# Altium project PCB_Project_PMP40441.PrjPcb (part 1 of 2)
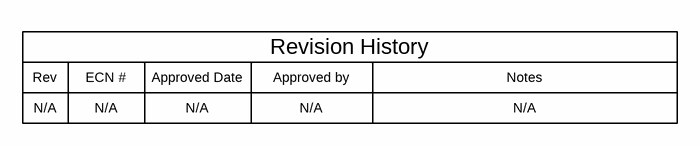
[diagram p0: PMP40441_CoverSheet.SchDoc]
TID: N/A; TechSupport: http://www.ti.com/support; SCH_Rev: E1; PRJ_Title: Multi-cell Buck-boost Battery Charger for PD PPS; PRJ_Number: PMP40441; PRJ_Engineer: San Chen; PRJ_Customer: Public Release; PCB_Rev: E1; PCB_Layout: Who did the Layout?; CopyrightYear: 2017
3 sheets, 208 parts. Net scope: global (net labels, ports and power ports of the same name join across sheets).
Board file: PMP40441_Layout.PcbDoc
Sheets:
  PMP40441_CoverSheet.SchDoc
  PMP40441_Main.SchDoc
  PMP40442_Main.SchDoc

## Sheet PMP40441_CoverSheet.SchDoc
size 431 x 279 mm; Date: Not shown in title block; ApprovedBy: Not shown in title block; CheckedBy: Not shown in title block; Author: Not shown in title block; CompanyName: Not shown in title block; Engineer: Not shown in title block; Organization: Not shown in title block; Address1: Not shown in title block; Address2: Not shown in title block; Address3: Not shown in title block; Address4: Not shown in title block; DocumentNumber: 1; Revision: Use project parameter SCH_Rev; SheetNumber: 1; SheetTotal: 3; PageSetup: Record=PageOptions¦CenterHorizontal=True¦CenterVertical=True¦PrintScale=1.00¦XCorrection=1.00¦YCorrection=1.00¦PrintKind=0¦BorderSize=5000000¦LeftOffset=0¦BottomOffset=0¦Orientation=2¦PaperLength=1000¦PaperWidth=1000¦Scale=100¦PaperSource=15¦PrintQuality=600¦MediaType=1¦DitherType=10¦PaperKind=Letter¦PrintScaleMode=1

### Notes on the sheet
- Rev
- N/A
- ECN #
- Approved Date
- Approved by
- Revision History
- Notes

## Sheet PMP40441_Main.SchDoc
size 431 x 279 mm; Date: Not shown in title block; ApprovedBy: Not shown in title block; CheckedBy: Not shown in title block; Author: Not shown in title block; CompanyName: Not shown in title block; Engineer: Not shown in title block; Organization: Not shown in title block; Address1: Not shown in title block; Address2: Not shown in title block; Address3: Not shown in title block; Address4: Not shown in title block; DocumentNumber: 2; Revision: Use project parameter SCH_Rev; SheetNumber: 2; SheetTotal: 3; PageSetup: Record=PageOptions¦CenterHorizontal=True¦CenterVertical=True¦PrintScale=1.00¦XCorrection=1.00¦YCorrection=1.00¦PrintKind=0¦BorderSize=5000000¦LeftOffset=0¦BottomOffset=0¦Orientation=2¦PaperLength=1000¦PaperWidth=1000¦Scale=100¦PaperSource=15¦PrintQuality=600¦MediaType=1¦DitherType=10¦PaperKind=Letter¦PrintScaleMode=1
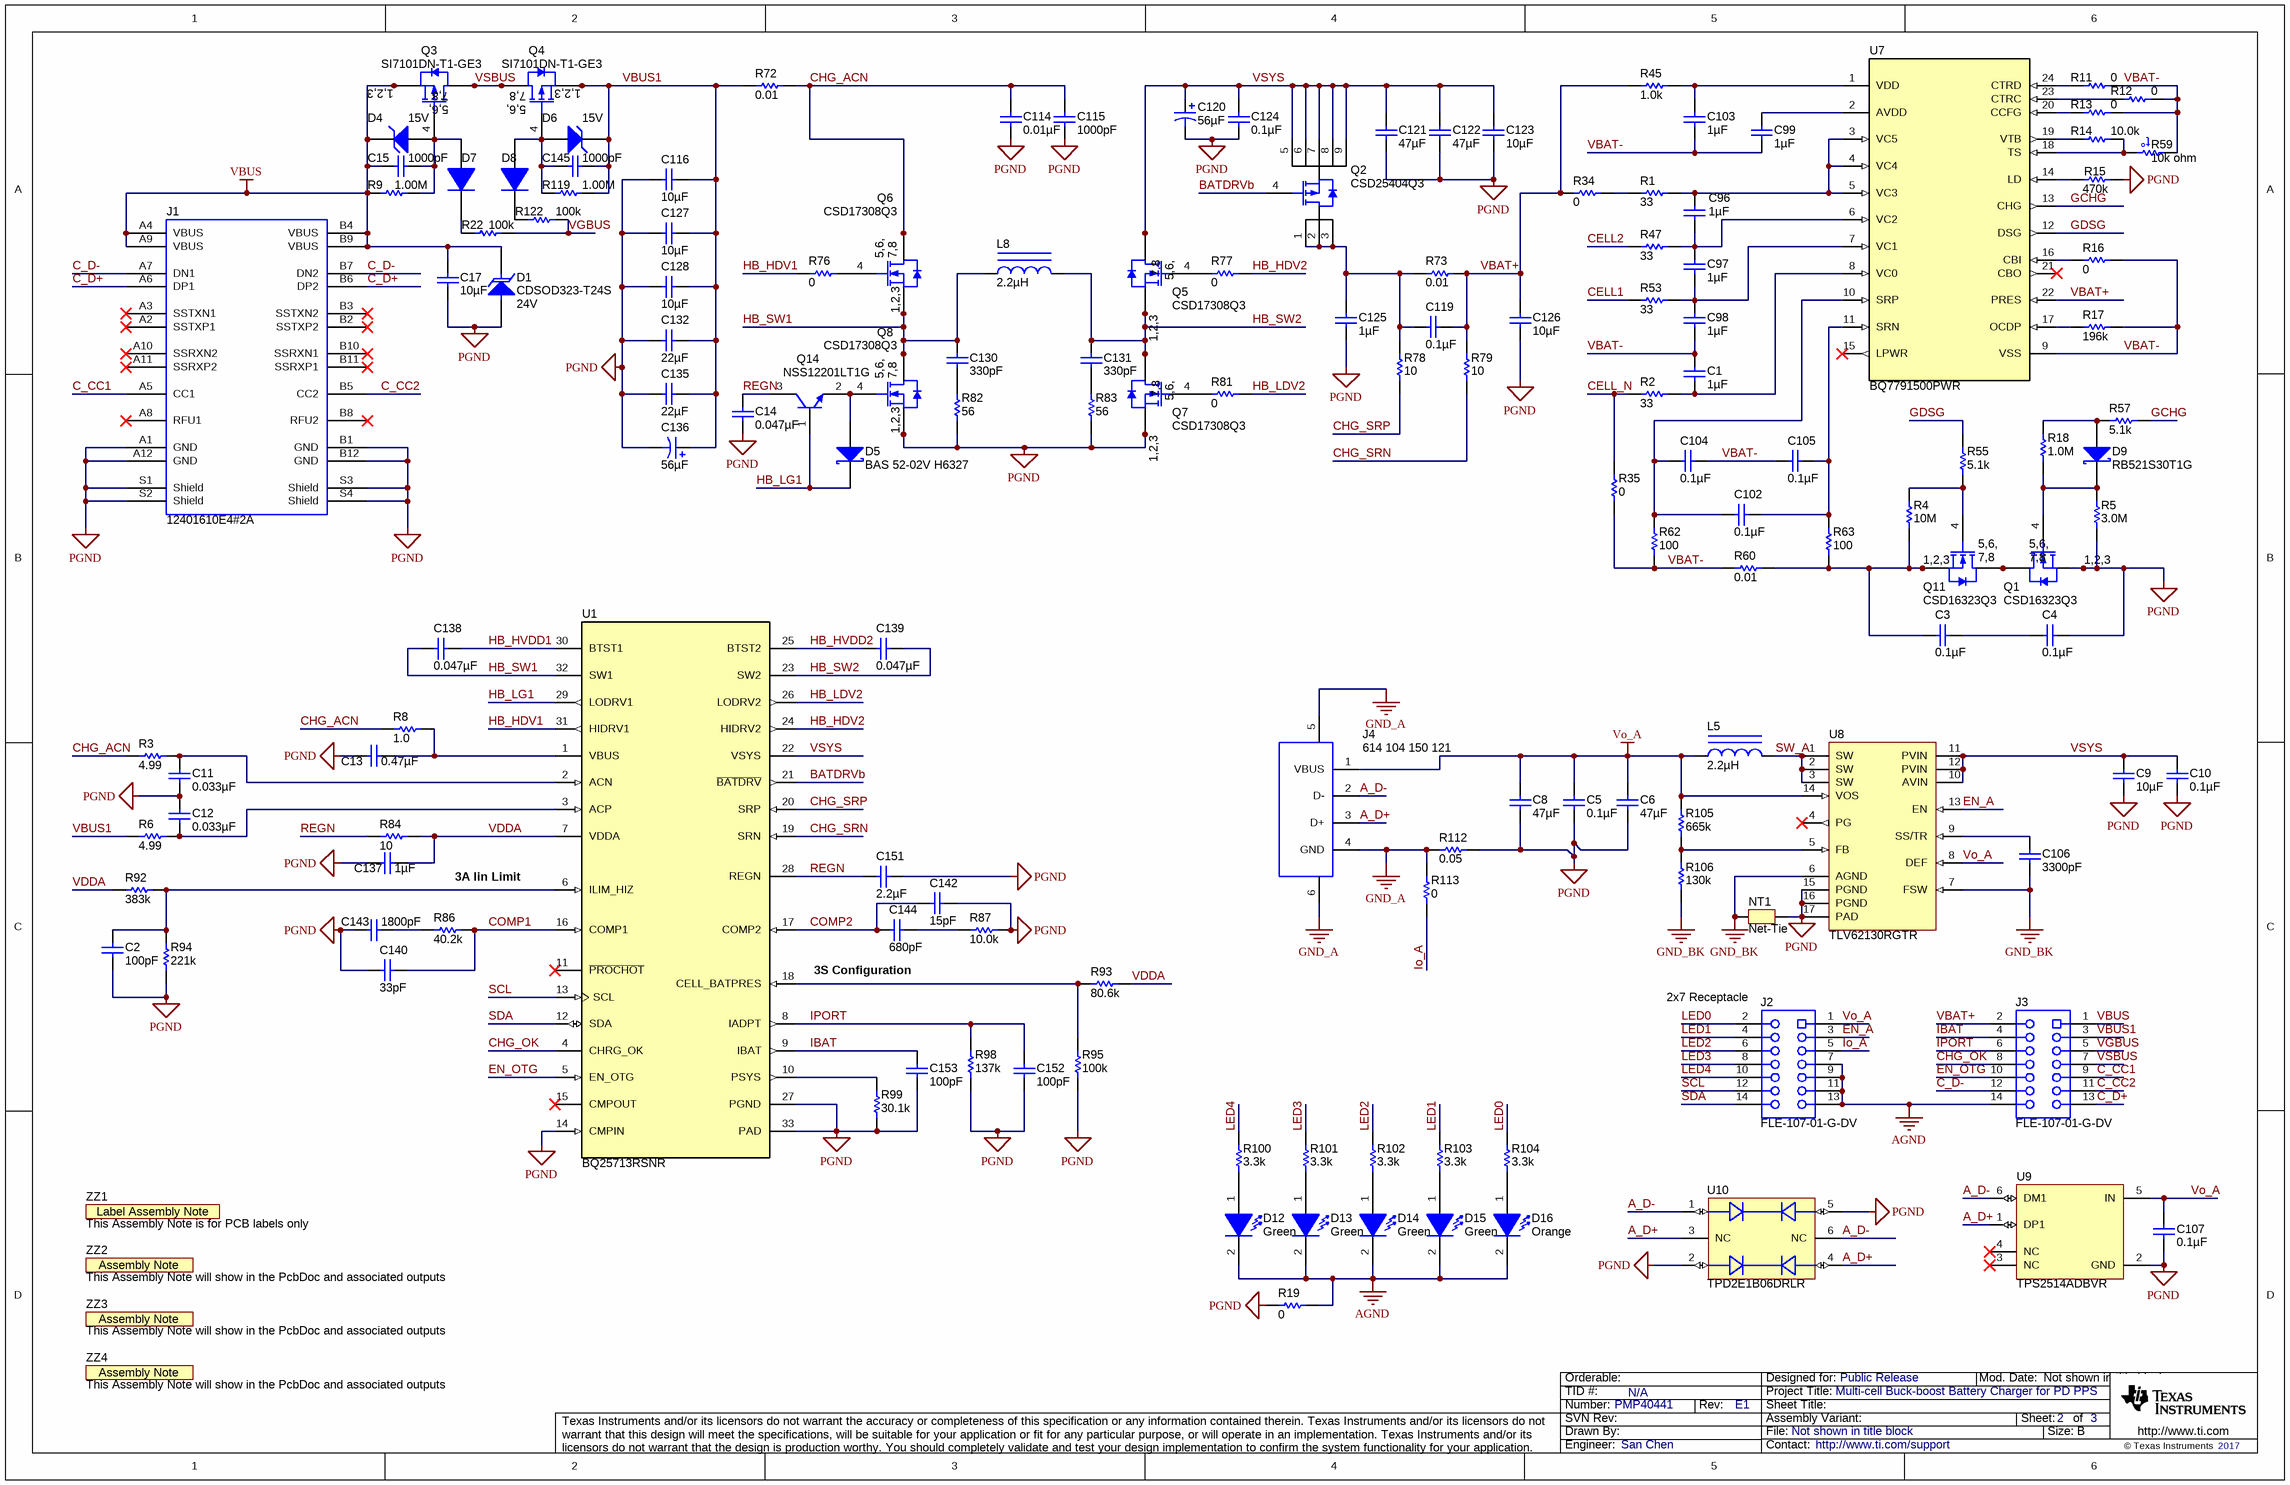
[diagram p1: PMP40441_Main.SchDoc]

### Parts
C1  ValueDisplayed: 1µF  [0402S]  (hidden comment: C1005X5R1C105K050BC)
C2  ValueDisplayed: 100pF  [0402]  (hidden comment: GRM1555C1H101JA01D)
C3  ValueDisplayed: 0.1µF  [0402]  (hidden comment: GRM155R61C104KA88D)
C4  ValueDisplayed: 0.1µF  [0402]  (hidden comment: GRM155R61C104KA88D)
C5  ValueDisplayed: 0.1µF  [0402]  (hidden comment: GRM155R61C104KA88D)
C6  ValueDisplayed: 47µF  [0805_HV]  (hidden comment: JMK212BJ476MG-T)
C8  ValueDisplayed: 47µF  [0805_HV]  (hidden comment: JMK212BJ476MG-T)
C9  ValueDisplayed: 10µF  [0603]  (hidden comment: GRM188R61E106MA73D)
C10  ValueDisplayed: 0.1µF  [0402]  (hidden comment: GRM155R61E104KA87D)
C11  ValueDisplayed: 0.033µF  [0603S]  (hidden comment: GRM188R71H333KA61D)
C12  ValueDisplayed: 0.033µF  [0603S]  (hidden comment: GRM188R71H333KA61D)
C13  ValueDisplayed: 0.47µF  [0805L]  (hidden comment: GRM21BR71H474KA88L)
C14  ValueDisplayed: 0.047µF  [0402]  (hidden comment: GRM155R61C473KA01D)
C15  ValueDisplayed: 1000pF  [0402]  (hidden comment: C0402C102J3RACTU)
C17  ValueDisplayed: 10µF  [0805_HV]  (hidden comment: GRM21BR6YA106KE43L)
C96  ValueDisplayed: 1µF  [0402S]  (hidden comment: C1005X5R1C105K050BC)
C97  ValueDisplayed: 1µF  [0402S]  (hidden comment: C1005X5R1C105K050BC)
C98  ValueDisplayed: 1µF  [0402S]  (hidden comment: C1005X5R1C105K050BC)
C99  ValueDisplayed: 1µF  [0402S]  (hidden comment: C1005X5R1C105K050BC)
C102  ValueDisplayed: 0.1µF  [0402S]  (hidden comment: GRM155R61C104KA88D)
C103  ValueDisplayed: 1µF  [0402S]  (hidden comment: C1005X5R1E105K050BC)
C104  ValueDisplayed: 0.1µF  [0402S]  (hidden comment: GRM155R61C104KA88D)
C105  ValueDisplayed: 0.1µF  [0402S]  (hidden comment: GRM155R61C104KA88D)
C106  ValueDisplayed: 3300pF  [0402]  (hidden comment: GRM155R71H332KA01D)
C107  ValueDisplayed: 0.1µF  [0402]  (hidden comment: GRM155R61C104KA88D)
C114  ValueDisplayed: 0.01µF  [0402S]  (hidden comment: GRM155R71H103KA88D)
C115  ValueDisplayed: 1000pF  [0402S]  (hidden comment: GRM155R61H102KA01D)
C116  ValueDisplayed: 10µF  [0805_HV]  (hidden comment: GRM21BR6YA106KE43L)
C119  ValueDisplayed: 0.1µF  [0402S]  (hidden comment: GRM155R61E104KA87D)
C120  ValueDisplayed: 56µF  [SM_RADIAL_6.3AMM]  (hidden comment: EEHZA1E560P)
C121  ValueDisplayed: 47µF  [1206_190]  (hidden comment: C3216X5R1E476M160AC)
C122  ValueDisplayed: 47µF  [1206_190]  (hidden comment: C3216X5R1E476M160AC)
C123  ValueDisplayed: 10µF  [0603]  (hidden comment: GRM188R61E106MA73D)
C124  ValueDisplayed: 0.1µF  [0402]  (hidden comment: GRM155R61E104KA87D)
C125  ValueDisplayed: 1µF  [0402S]  (hidden comment: GRM155R61E105KA12D)
C126  ValueDisplayed: 10µF  [0603]  (hidden comment: GRM188R61E106MA73D)
C127  ValueDisplayed: 10µF  [0805_HV]  (hidden comment: GRM21BR6YA106KE43L)
C128  ValueDisplayed: 10µF  [0805_HV]  (hidden comment: GRM21BR6YA106KE43L)
C130  ValueDisplayed: 330pF  [0402S]  (hidden comment: GRM1555C1H331JA01D)
C131  ValueDisplayed: 330pF  [0402S]  (hidden comment: GRM1555C1H331JA01D)
C132  ValueDisplayed: 22µF  [1206_190]  (hidden comment: C3216X5R1V226M160AC)
C135  ValueDisplayed: 22µF  [1206_190]  (hidden comment: C3216X5R1V226M160AC)
C136  ValueDisplayed: 56µF  [SM_RADIAL_6.3AMM]  (hidden comment: EEHZA1E560P)
C137  ValueDisplayed: 1µF  [0402]  (hidden comment: C1005X5R1C105K050BC)
C138  ValueDisplayed: 0.047µF  [0402]  (hidden comment: GRM155R61C473KA01D)
C139  ValueDisplayed: 0.047µF  [0402]  (hidden comment: GRM155R61C473KA01D)
C140  ValueDisplayed: 33pF  [0402]  (hidden comment: GRM1555C1H330JA01D)
C142  ValueDisplayed: 15pF  [0402]  (hidden comment: GRM1555C1H150JA01D)
C143  ValueDisplayed: 1800pF  [0402]  (hidden comment: GRM155R71H182KA01D)
C144  ValueDisplayed: 680pF  [0402]  (hidden comment: GRM1555C1H681JA01D)
C145  ValueDisplayed: 1000pF  [0402]  (hidden comment: C0402C102J3RACTU)
C151  ValueDisplayed: 2.2µF  [0402]  (hidden comment: C1005X5R1C225K050BC)
C152  ValueDisplayed: 100pF  [0402]  (hidden comment: GRM1555C1H101JA01D)
C153  ValueDisplayed: 100pF  [0402]  (hidden comment: GRM1555C1H101JA01D)
D1  CDSOD323-T24S  value 24V  [SOD-323]
D4  value 15V  [SOD-323]  (hidden comment: BZX384-C15,115)
D5  BAS 52-02V H6327  [SOD-523]
D6  value 15V  [SOD-323]  (hidden comment: BZX384-C15,115)
D7  1N4148WX-TP  [SOD-323]  (value not drawn)
D8  1N4148WX-TP  [SOD-323]  (value not drawn)
D9  RB521S30T1G  [SOD-523]
D12  value Green  [LED_LTST-C190]  (hidden comment: LTST-C190GKT)
D13  value Green  [LED_LTST-C190]  (hidden comment: LTST-C190GKT)
D14  value Green  [LED_LTST-C190]  (hidden comment: LTST-C190GKT)
D15  value Green  [LED_LTST-C190]  (hidden comment: LTST-C190GKT)
D16  value Orange  [LED_LTST-C190]  (hidden comment: LTST-C190KFKT)
J1  12401610E4#2A  [Amphenol_12401610E4_2A]
J2  FLE-107-01-G-DV  [Samtec_FLE-107-01-x-DV]
J3  FLE-107-01-G-DV  [Samtec_FLE-107-01-x-DV]
J4  614 104 150 121  [WURTH_614104150121]
L5  ValueDisplayed: 2.2µH  [XFL4020]  (hidden comment: XFL4020-222MEB)
L8  ValueDisplayed: 2.2µH  [XEL6060]  (hidden comment: XEL6060-222MEB)
NT1  Net-Tie  [Net-Tie_10mil]  (net tie, no BOM)
Q1  CSD16323Q3  [DQG0008A]
Q2  CSD25404Q3  [DQG0008A]
Q3  SI7101DN-T1-GE3  [PowerPAK_1212-8]
Q4  SI7101DN-T1-GE3  [PowerPAK_1212-8]
Q5  CSD17308Q3  [DQG0008A]
Q6  CSD17308Q3  [DQG0008A]
Q7  CSD17308Q3  [CSD17308Q3]
Q8  CSD17308Q3  [DQG0008A]
Q11  CSD16323Q3  [DQG0008A]
Q14  NSS12201LT1G  [SOT-23]
R1  ValueDisplayed: 33  [0805L]  (hidden comment: CRCW080533R0JNEA)
R2  ValueDisplayed: 33  [0805L]  (hidden comment: CRCW080533R0JNEA)
R3  ValueDisplayed: 4.99  [0402S]  (hidden comment: CRCW04024R99FKED)
R4  ValueDisplayed: 10M  [0402]  (hidden comment: CRCW040210M0JNED)
R5  ValueDisplayed: 3.0M  [0402]  (hidden comment: CRCW04023M00JNED)
R6  ValueDisplayed: 4.99  [0402S]  (hidden comment: CRCW04024R99FKED)
R8  ValueDisplayed: 1.0  [0402]  (hidden comment: CRCW04021R00JNED)
R9  ValueDisplayed: 1.00M  [0402]  (hidden comment: RC0402FR-071ML)
R11  ValueDisplayed: 0  [0402S]  (hidden comment: CRCW04020000Z0ED)
R12  ValueDisplayed: 0  [0402S]  (hidden comment: CRCW04020000Z0ED)
R13  ValueDisplayed: 0  [0402S]  (hidden comment: CRCW04020000Z0ED)
R14  ValueDisplayed: 10.0k  [0402S]  (hidden comment: CRCW040210K0FKED)
R15  ValueDisplayed: 470k  [0402S]  (hidden comment: CRCW0402470KJNED)
R16  ValueDisplayed: 0  [0402S]  (hidden comment: CRCW04020000Z0ED)
R17  ValueDisplayed: 196k  [0402S]  (hidden comment: CRCW0402196KFKED)
R18  ValueDisplayed: 1.0M  [0402]  (hidden comment: CRCW04021M00JNED)
R19  ValueDisplayed: 0  [0402]  (hidden comment: CRCW04020000Z0ED)
R22  ValueDisplayed: 100k  [0402]  (hidden comment: RG1005P-104-B-T5)
R34  ValueDisplayed: 0  [0402S]  (hidden comment: CRCW04020000Z0ED)
R35  ValueDisplayed: 0  [0402S]  (hidden comment: CRCW04020000Z0ED)
R45  ValueDisplayed: 1.0k  [0402S]  (hidden comment: CRCW04021K00JNED)
R47  ValueDisplayed: 33  [0805L]  (hidden comment: CRCW080533R0JNEA)
R53  ValueDisplayed: 33  [0805L]  (hidden comment: CRCW080533R0JNEA)
R55  ValueDisplayed: 5.1k  [0402S]  (hidden comment: CRCW04025K10JNED)
R57  ValueDisplayed: 5.1k  [0402S]  (hidden comment: CRCW04025K10JNED)
R59  value 10k ohm  [0402S]  (hidden comment: ERT-J0EG103HA)
R60  ValueDisplayed: 0.01  [1206]  (hidden comment: WSLP1206R0100FEA)
R62  ValueDisplayed: 100  [0402]  (hidden comment: CRCW0402100RFKED)
R63  ValueDisplayed: 100  [0402]  (hidden comment: CRCW0402100RFKED)
R72  ValueDisplayed: 0.01  [1206]  (hidden comment: WSLP1206R0100FEA)
R73  ValueDisplayed: 0.01  [1206]  (hidden comment: WSLP1206R0100FEA)
R76  ValueDisplayed: 0  [0402S]  (hidden comment: CRCW04020000Z0ED)
R77  ValueDisplayed: 0  [0402S]  (hidden comment: CRCW04020000Z0ED)
R78  ValueDisplayed: 10  [0402S]  (hidden comment: CRCW040210R0JNED)
R79  ValueDisplayed: 10  [0402S]  (hidden comment: CRCW040210R0JNED)
R81  ValueDisplayed: 0  [0402S]  (hidden comment: CRCW04020000Z0ED)
R82  ValueDisplayed: 56  [0603S]  (hidden comment: CRCW060356R0JNEA)
R83  ValueDisplayed: 56  [0603S]  (hidden comment: CRCW060356R0JNEA)
R84  ValueDisplayed: 10  [0402]  (hidden comment: CRCW040210R0JNED)
R86  ValueDisplayed: 40.2k  [0402]  (hidden comment: CRCW040240K2FKED)
R87  ValueDisplayed: 10.0k  [0402]  (hidden comment: CRCW040210K0FKED)
R92  ValueDisplayed: 383k  [0402L]  (hidden comment: CRCW0402383KFKED)
R93  ValueDisplayed: 80.6k  [0402]  (hidden comment: CRCW040280K6FKED)
R94  ValueDisplayed: 221k  [0402]  (hidden comment: CRCW0402221KFKED)
R95  ValueDisplayed: 100k  [0402]  (hidden comment: CRCW0402100KFKED)
R98  ValueDisplayed: 137k  [0402]  (hidden comment: CRCW0402137KFKED)
R99  ValueDisplayed: 30.1k  [0402]  (hidden comment: CRCW040230K1FKED)
R100  ValueDisplayed: 3.3k  [0402]  (hidden comment: CRCW04023K30JNED)
R101  ValueDisplayed: 3.3k  [0402]  (hidden comment: CRCW04023K30JNED)
R102  ValueDisplayed: 3.3k  [0402]  (hidden comment: CRCW04023K30JNED)
R103  ValueDisplayed: 3.3k  [0402]  (hidden comment: CRCW04023K30JNED)
R104  ValueDisplayed: 3.3k  [0402]  (hidden comment: CRCW04023K30JNED)
R105  ValueDisplayed: 665k  [0402S]  (hidden comment: CRCW0402665KFKED)
R106  ValueDisplayed: 130k  [0402S]  (hidden comment: CRCW0402130KFKED)
R112  ValueDisplayed: 0.05  [1206]  (hidden comment: ERJ-8CWFR050V)
R113  ValueDisplayed: 0  [0402S]  (hidden comment: CRCW04020000Z0ED)
R119  ValueDisplayed: 1.00M  [0402]  (hidden comment: RC0402FR-071ML)
R122  ValueDisplayed: 100k  [0402]  (hidden comment: RG1005P-104-B-T5)
U1  BQ25713RSNR  [RSN0032B]
U7  BQ7791500PWR  [PW0024A_N]
U8  TLV62130RGTR  [RGT0016C]
U9  TPS2514ADBVR  [DBV0006A_N]
U10  TPD2E1B06DRLR  [DRL0006A]
ZZ1  This Assembly Note is for PCB labels only  [AssemblyNoteLabel]  (no BOM)
ZZ2  This Assembly Note will show in the PcbDoc and associated outputs  [AssemblyNote]  (no BOM)
ZZ3  This Assembly Note will show in the PcbDoc and associated outputs  [AssemblyNote]  (no BOM)
ZZ4  This Assembly Note will show in the PcbDoc and associated outputs  [AssemblyNote]  (no BOM)

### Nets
AGND: D12.2(K) D13.2(K) D14.2(K) D15.2(K) D16.2(K) J2.7 J2.9 J2.11 J2.13 J3.14 R19.2
GND_A: J4.4(GND) J4.5(Shield) J4.6(Shield) R112.2 R113.2
GND_BK: C106.1 NT1.1 R106.1 U8.6(AGND) U8.7(FSW)
PGND: C2.2 C4.1 C5.1 C6.2 C8.2 C9.2 C10.2 C11.2 C12.1 C13.1 C14.1 C17.2 C107.2 C114.2 C115.2 C116.2 C120.2(-) C121.2 C122.2 C123.2 C124.2 C125.2 C126.2 C127.1 C128.1 C132.1 C135.1 C136.2(-) C137.2 C140.2 C142.1 C143.2 C151.1 C152.2 C153.2 D1.2(A) J1.A1(GND) J1.A12(GND) J1.B1(GND) J1.B12(GND) J1.S1(Shield) J1.S2(Shield) J1.S3(Shield) J1.S4(Shield) NT1.2 Q1.1(S) Q1.2(S) Q1.3(S) Q7.1(S) Q7.2(S) Q7.3(S) Q8.1(S) Q8.2(S) Q8.3(S) R5.2 R15.2 R19.1 R82.1 R83.1 R87.2 R94.2 R95.1 R98.2 R99.2 R112.1 U1.14(CMPIN) U1.27(PGND) U1.33(PAD) U8.15(PGND) U8.16(PGND) U8.17(PAD) U9.2(GND) U10.2(IOB1) U10.5(IOA2)
VBUS: C15.2 C17.1 D1.1(K) D4.1(K) J1.A4(VBUS) J1.A9(VBUS) J1.B4(VBUS) J1.B9(VBUS) J3.1 Q3.1(S) Q3.2(S) Q3.3(S) R9.1
Vo_A: C5.2 C6.1 C8.1 C107.1 J2.1 J4.1(VBUS) L5.1 R105.2 U8.8(DEF) U8.14(VOS) U9.5(IN)
A_D+: J4.3(D+) U9.1(DP1) U10.3(NC) U10.4(IOB2)
A_D-: J4.2(D-) U9.6(DM1) U10.1(IOA1) U10.6(NC)
BATDRVb: Q2.4(G) U1.21(~{BATDRV})
C_CC1: J1.A5(CC1) J3.9
C_CC2: J1.B5(CC2) J3.11
C_D+: J1.A6(DP1) J1.B6(DP2) J3.13
C_D-: J1.A7(DN1) J1.B7(DN2) J3.12
CELL1: R53.2
CELL2: R47.2
CELL_N: R2.2 R35.1
CHG_ACN: C114.1 C115.1 Q6.5(D) Q6.6(D) Q6.7(D) Q6.8(D) Q6.9(D) R3.1 R8.1 R72.2
CHG_OK: J3.8 U1.4(CHRG_OK)
CHG_SRN: R79.1 U1.19(SRN)
CHG_SRP: R78.1 U1.20(SRP)
COMP1: C140.1 R86.2 U1.16(COMP1)
COMP2: C142.2 C144.2 U1.17(COMP2)
EN_A: J2.3 U8.13(EN)
EN_OTG: J3.10 U1.5(EN_OTG)
GCHG: R57.2 U7.13(CHG)
GDSG: R55.1 U7.12(DSG)
HB_HDV1: R76.1 U1.31(HIDRV1)
HB_HDV2: R77.2 U1.24(HIDRV2)
HB_HVDD1: C138.2 U1.30(BTST1)
HB_HVDD2: C139.1 U1.25(BTST2)
HB_LDV2: R81.2 U1.26(LODRV2)
HB_LG1: D5.1(K) Q14.1(B) U1.29(LODRV1)
HB_SW1: C130.1 C138.1 L8.1 Q6.1(S) Q6.2(S) Q6.3(S) Q8.5(D) Q8.6(D) Q8.7(D) Q8.8(D) Q8.9(D) U1.32(SW1)
HB_SW2: C131.1 C139.2 L8.2 Q5.1(S) Q5.2(S) Q5.3(S) Q7.5(D) Q7.6(D) Q7.7(D) Q7.8(D) Q7.9(D) U1.23(SW2)
IBAT: C153.1 J3.4 U1.9(IBAT)
Io_A: J2.5 R113.1
IPORT: C152.1 J3.6 R98.1 U1.8(IADPT)
LED0: J2.2 R104.2
LED1: J2.4 R103.2
LED2: J2.6 R102.2
LED3: J2.8 R101.2
LED4: J2.10 R100.2
REGN: C14.2 C151.2 Q14.3(C) R84.2 U1.28(REGN)
SCL: J2.12 U1.13(SCL)
SDA: J2.14 U1.12(SDA)
SW_A: L5.2 U8.1(SW) U8.2(SW) U8.3(SW)
VBAT+: C119.1 C126.1 J3.2 R34.2 R45.2 R73.2 R79.2 U7.22(PRES)
VBAT-: C1.1 C98.2 C99.2 C103.2 C104.1 C105.2 R11.2 R12.2 R13.2 R16.2 R17.2 R35.2 R59.1 R60.1 R62.2 U7.9(VSS)
VBUS1: C116.1 C127.2 C128.2 C132.2 C135.2 C136.1(+) C145.1 D6.1(K) J3.3 Q4.1(S) Q4.2(S) Q4.3(S) R6.1 R72.1 R119.1
VDDA: C137.1 R84.1 R92.1 R93.2 U1.7(VDDA)
VGBUS: J3.5 R22.2 R122.2
VSBUS: J3.7 Q3.5(D) Q3.6(D) Q3.7(D) Q3.8(D) Q3.9(D) Q4.5(D) Q4.6(D) Q4.7(D) Q4.8(D) Q4.9(D)
VSYS: C9.1 C10.1 C120.1(+) C121.1 C122.1 C123.1 C124.1 Q2.5(S) Q2.6(S) Q2.7(S) Q2.8(S) Q2.9(S) Q5.5(D) Q5.6(D) Q5.7(D) Q5.8(D) Q5.9(D) U1.22(VSYS) U8.10(AVIN) U8.11(PVIN) U8.12(PVIN)
NetC1_2: C1.2 R2.1 U7.8(VC0)
NetC2_1: C2.1 R92.2 R94.1 U1.6(ILIM_HIZ)
NetC3_1: C3.1 C4.2
NetC3_2: C3.2 Q11.1(S) Q11.2(S) Q11.3(S) R4.2 R60.2 R63.2
NetC11_1: C11.1 R3.2 U1.2(ACN)
NetC12_2: C12.2 R6.2 U1.3(ACP)
NetC13_2: C13.2 R8.2 U1.1(VBUS)
NetC15_1: C15.1 D4.2(A) D7.2(A) Q3.4(G) R9.2
NetC96_1: C96.1 R1.1 U7.3(VC5) U7.4(VC4) U7.5(VC3)
NetC96_2: C96.2 C97.1 R47.1 U7.6(VC2)
NetC97_2: C97.2 C98.1 R53.1 U7.7(VC1)
NetC99_1: C99.1 U7.2(AVDD)
NetC102_1: C102.1 C104.2 R62.1 U7.10(SRP)
NetC102_2: C102.2 C105.1 R63.1 U7.11(SRN)
NetC103_1: C103.1 R45.1 U7.1(VDD)
NetC106_2: C106.2 U8.9(SS/TR)
NetC119_2: C119.2 C125.1 Q2.1(D) Q2.2(D) Q2.3(D) R73.1 R78.2
NetC130_2: C130.2 R82.2
NetC131_2: C131.2 R83.2
NetC143_1: C143.1 R86.1
NetC144_1: C144.1 R87.1
NetC145_2: C145.2 D6.2(A) D8.2(A) Q4.4(G) R119.2
NetD5_2: D5.2(A) Q8.4(G) Q14.2(E)
NetD7_1: D7.1(K) R22.1
NetD8_1: D8.1(K) R122.1
NetD9_1: D9.1(K) Q1.4(G) R5.1 R18.2
NetD9_2: D9.2(A) R18.1 R57.1
NetD12_1: D12.1(A) R100.1
NetD13_1: D13.1(A) R101.1
NetD14_1: D14.1(A) R102.1
NetD15_1: D15.1(A) R103.1
NetD16_1: D16.1(A) R104.1
NetQ1_5: Q1.5(D) Q1.6(D) Q1.7(D) Q1.8(D) Q1.9(D) Q11.5(D) Q11.6(D) Q11.7(D) Q11.8(D) Q11.9(D)
NetQ5_4: Q5.4(G) R77.1
NetQ6_4: Q6.4(G) R76.2
NetQ7_4: Q7.4(G) R81.1
NetQ11_4: Q11.4(G) R4.1 R55.2
NetR1_2: R1.2 R34.1
NetR11_1: R11.1 U7.24(CTRD)
NetR12_1: R12.1 U7.23(CTRC)
NetR13_1: R13.1 U7.20(CCFG)
NetR14_1: R14.1 R59.2 U7.18(TS)
NetR14_2: R14.2 U7.19(VTB)
NetR15_1: R15.1 U7.14(LD)
NetR16_1: R16.1 U7.16(CBI)
NetR17_1: R17.1 U7.17(OCDP)
NetR93_1: R93.1 R95.2 U1.18(CELL_BATPRES)
NetR99_1: R99.1 U1.10(PSYS)
NetR105_1: R105.1 R106.2 U8.5(FB)

Not connected (* = marked no-connect by the designer): J1 A2(SSTXP1)* A3(SSTXN1)* A8(RFU1)* A10(SSRXN2)* A11(SSRXP2)* B2(SSTXP2)* B3(SSTXN2)* B8(RFU2)* B10(SSRXN1)* B11(SSRXP1)*; U1 11(~{PROCHOT})* 15(CMPOUT)*; U7 15(LPWR)* 21(CBO)*; U8 4(PG)*; U9 3(NC)* 4(NC)*

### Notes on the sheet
- 3A Iin Limit
- 3S Configuration
- (near J2) 2x7 Receptacle

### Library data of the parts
C1 C96-C99 = C1005X5R1C105K050BC: CAP, CERM, 1 µF, 16 V,+/- 10%, X5R, 0402; Manufacturer: TDK; Polarized: N; CompType: Capacitor; Value: 1uF; U/M: EA; Cap_F: 0.000001; Tolerance_%: 10; VDC_V: 16; Value2: 16V; TaMin_C: -55; TaMax_C: 85; Cap_Case: 0402; AEC Category: Q200; SizeArea_mm2: 0.5; SizeAreaWB_mm2: 3; SizeX_mm: 1; SizeZ_mm: 0.6; Green_Lifecycle: EOL; Green_REACh: Passed
C2 = GRM1555C1H101JA01D: CAP, CERM, 100 pF, 50 V, +/- 5%, C0G/NP0, 0402; Manufacturer: MuRata; Polarized: N; CompType: Capacitor; Value: 100pF; U/M: EA; Cap_F: 0.0000000001; Tolerance_%: 5; Value1: Unknown; VDC_V: 50; Value2: 50V; TaMin_C: -55; TaMax_C: 125; AEC Category: Q200; SizeArea_mm2: 0.5; SizeAreaWB_mm2: 3; SizeX_mm: 1; SizeZ_mm: 0.6
C3-C5 C107 = GRM155R61C104KA88D: CAP, CERM, 0.1 µF, 16 V, +/- 10%, X5R, 0402; Manufacturer: MuRata; Polarized: N; CompType: Capacitor; Value: 0.1uF; U/M: EA; Cap_F: 0.0000001; Tolerance_%: 10; Value1: Unknown; VDC_V: 16; Value2: 16V; TaMin_C: -55; TaMax_C: 85; AEC Category: Q200
C6 C8 = JMK212BJ476MG-T: CAP, CERM, 47 µF, 6.3 V, +/- 20%, X5R, 0805; Manufacturer: Taiyo Yuden; Polarized: N; CompType: Capacitor; Value: 47uF; U/M: EA; Cap_F: 0.000047; Tolerance_%: 20; Value1: Unknown; VDC_V: 6.3; Value2: 6.3V; TaMin_C: -55; TaMax_C: 85; Cap_Case: 0805
C9 C123 = GRM188R61E106MA73D: CAP, CERM, 10 µF, 25 V, +/- 20%, X5R, 0603; Manufacturer: MuRata; Polarized: N; CompType: Capacitor; Value: 10uF; U/M: EA; Cap_F: 0.00001; Tolerance_%: 20; Value1: Unknown; VDC_V: 25; Value2: 25V; TaMin_C: -55; TaMax_C: 85; AEC Category: Q200
C10 C124 = GRM155R61E104KA87D: CAP, CERM, 0.1 µF, 25 V, +/- 10%, X5R, 0402; Manufacturer: MuRata; Polarized: N; CompType: Capacitor; Value: 0.1uF; U/M: EA; Cap_F: 0.0000001; Tolerance_%: 10; Value1: Unknown; VDC_V: 25; Value2: 25V; TaMin_C: -55; TaMax_C: 85; AEC Category: Q200
C11 C12 = GRM188R71H333KA61D: CAP, CERM, 0.033 µF, 50 V, +/- 10%, X7R, 0603; Manufacturer: MuRata; Polarized: N; CompType: Capacitor; Value: 0.033uF; U/M: EA; Cap_F: 0.000000033; Tolerance_%: 10; Value1: Unknown; VDC_V: 50; Value2: 50V; TaMin_C: -55; TaMax_C: 125; Cap_Case: 0603; AEC Category: Q200; SizeArea_mm2: 1.28; SizeAreaWB_mm2: 4.68; SizeX_mm: 1.6; SizeY_mm: 0.8; SizeZ_mm: 1
C13 = GRM21BR71H474KA88L: CAP, CERM, 0.47 µF, 50 V, +/- 10%, X7R, 0805; Manufacturer: MuRata; Polarized: N; CompType: Capacitor; Value: 0.47uF; U/M: EA; Cap_F: 0.00000047; Tolerance_%: 10; Value1: Unknown; VDC_V: 50; Value2: 50V; TaMin_C: -55; TaMax_C: 125; Cap_Case: 0805; AEC Category: Q200; SizeArea_mm2: 2.5; SizeAreaWB_mm2: 6.75; SizeX_mm: 2; SizeY_mm: 1.25; SizeZ_mm: 1.45
C14 = GRM155R61C473KA01D: CAP, CERM, 0.047 µF, 16 V, +/- 10%, X5R, 0402; Manufacturer: MuRata; Polarized: N; CompType: Capacitor; Value: 0.047uF; U/M: EA; Cap_F: 0.000000047; Tolerance_%: 10; Value1: Unknown; VDC_V: 16; Value2: 16V; TaMin_C: -55; TaMax_C: 85; AEC Category: Q200; SizeArea_mm2: 0.5; SizeAreaWB_mm2: 3; SizeX_mm: 1; SizeZ_mm: 0.6
C15 C145 = CMP-0006234-2: CAP, CERM, 1000 pF, 25 V, +/- 5%, X7R, 0402; Manufacturer: Kemet; TaMin_C: -55°C; Polarized: N; SizeAreaWB_mm2: 3; Value1: Unknown; U/M: EA; Value: 1000pF; TaMax_C: 125°C; SizeZ_mm: 0.6; SizeX_mm: 1; SizeY_mm: 0.5; Value2: 25V; CompType: Capacitor; Cap_F: 1nF; AEC Category: Q200
C17 C116 = GRM21BR6YA106KE43L: CAP, CERM, 10 µF, 35 V, +/- 10%, X5R, 0805; Manufacturer: MuRata; Polarized: N; CompType: Capacitor; Value: 10uF; U/M: EA; Cap_F: 0.00001; Tolerance_%: 10; Value1: Unknown; VDC_V: 35; Value2: 35V; TaMin_C: -55; TaMax_C: 85; Cap_Case: 0805; AEC Category: Q200
C102 C104 C105 = GRM155R61C104KA88D: CAP, CERM, 0.1 µF, 16 V, +/- 10%, X5R, 0402; Manufacturer: MuRata; Polarized: N; CompType: Capacitor; Value: 0.1uF; U/M: EA; Cap_F: 0.0000001; Tolerance_%: 10; Value1: Unknown; VDC_V: 16; Value2: 16V; TaMin_C: -55; TaMax_C: 85; Cap_Case: 0402; AEC Category: Q200
C103 = C1005X5R1E105K050BC: CAP, CERM, 1 µF, 25 V, +/- 10%, X5R, 0402; Manufacturer: TDK; Polarized: N; CompType: Capacitor; Value: 1uF; U/M: EA; Cap_F: 0.000001; Tolerance_%: 10; Value1: Unknown; VDC_V: 25; Value2: 25V; TaMin_C: -55; TaMax_C: 80; Cap_Case: 0402; AEC Category: Q200
C106 = GRM155R71H332KA01D: CAP, CERM, 3300 pF, 50 V, +/- 10%, X7R, 0402; Manufacturer: MuRata; Polarized: N; CompType: Capacitor; Value: 3300pF; U/M: EA; Cap_F: 0.0000000033; Tolerance_%: 10; Value1: Unknown; VDC_V: 50; Value2: 50V; TaMin_C: -55; TaMax_C: 125; AEC Category: Q200
C114 = GRM155R71H103KA88D: CAP, CERM, 0.01 µF, 50 V, +/- 10%, X7R, 0402; Manufacturer: MuRata; Polarized: N; CompType: Capacitor; Value: 0.01uF; U/M: EA; Cap_F: 0.00000001; Tolerance_%: 10; Value1: Unknown; VDC_V: 50; Value2: 50V; TaMin_C: -55; TaMax_C: 125; Cap_Case: 0402; AEC Category: Q200
C115 = GRM155R61H102KA01D: CAP, CERM, 1000 pF, 50 V, +/- 10%, X5R, 0402; Manufacturer: MuRata; Polarized: N; CompType: Capacitor; Value: 1000pF; U/M: EA; Cap_F: 0.000000001; Tolerance_%: 10; Value1: Unknown; VDC_V: 50; Value2: 50V; TaMin_C: -55; TaMax_C: 85; Cap_Case: 0402; AEC Category: Q200
C119 = GRM155R61E104KA87D: CAP, CERM, 0.1 µF, 25 V, +/- 10%, X5R, 0402; Manufacturer: MuRata; Polarized: N; CompType: Capacitor; Value: 0.1uF; U/M: EA; Cap_F: 0.0000001; Tolerance_%: 10; Value1: Unknown; VDC_V: 25; Value2: 25V; TaMin_C: -55; TaMax_C: 85; Cap_Case: 0402; AEC Category: Q200
C120 C136 = EEHZA1E560P: CAP, Polymer Hybrid, 56 µF, 25 V, +/- 20%, 50 ohm, 6.3x5.8 SMD; Manufacturer: Panasonic; Polarized: Y; CompType: Capacitor; Value: 56uF; U/M: EA; Cap_F: 0.000056; Tolerance_%: 20; ESR_ohm: 50; Value1: 50 ohm; VDC_V: 25; Value2: 25V; IRMS_A: 1.3; TaMin_C: -55; TaMax_C: 105; AEC Category: Q200
C121 C122 = C3216X5R1E476M160AC: CAP, CERM, 47 µF, 25 V, +/- 20%, X5R, 1206_190; Manufacturer: TDK; Polarized: N; CompType: Capacitor; Value: 47uF; U/M: EA; Cap_F: 0.000047; Tolerance_%: 20; Value1: Unknown; VDC_V: 25; Value2: 25V; TaMin_C: -55; TaMax_C: 85; Cap_Case: 1206; AEC Category: Q200
C125 = GRM155R61E105KA12D: CAP, CERM, 1 µF, 25 V, +/- 10%, X5R, 0402; Manufacturer: MuRata; Polarized: N; CompType: Capacitor; Value: 1uF; U/M: EA; Cap_F: 0.000001; Tolerance_%: 10; Value1: Unknown; VDC_V: 25; Value2: 25V; TaMin_C: -55; TaMax_C: 85; Cap_Case: 0402; AEC Category: Q200; SizeArea_mm2: 0.5; SizeAreaWB_mm2: 3; SizeX_mm: 1; SizeZ_mm: 0.6
C126 = GRM188R61E106MA73D: CAP, CERM, 10 µF, 25 V, +/- 20%, X5R, 0603; Manufacturer: MuRata; Polarized: N; CompType: Capacitor; Value: 10uF; U/M: EA; Cap_F: 0.00001; Tolerance_%: 20; Value1: Unknown; VDC_V: 25; Value2: 25V; TaMin_C: -55; TaMax_C: 85; AEC Category: Q200; SizeArea_mm2: 1.28; SizeAreaWB_mm2: 4.68; SizeX_mm: 1.6; SizeY_mm: 0.8; SizeZ_mm: 1
C127 C128 = GRM21BR6YA106KE43L: CAP, CERM, 10 µF, 35 V, +/- 10%, X5R, 0805; Manufacturer: MuRata; Polarized: N; CompType: Capacitor; Value: 10uF; U/M: EA; Cap_F: 0.00001; Tolerance_%: 10; Value1: Unknown; VDC_V: 35; Value2: 35V; TaMin_C: -55; TaMax_C: 85; Cap_Case: 0805; AEC Category: Q200; SizeArea_mm2: 2.5; SizeAreaWB_mm2: 6.75; SizeX_mm: 2; SizeY_mm: 1.25; SizeZ_mm: 1.45
C130 C131 = GRM1555C1H331JA01D: CAP, CERM, 330 pF, 50 V, +/- 5%, C0G/NP0, 0402; Manufacturer: MuRata; Polarized: N; CompType: Capacitor; Value: 330pF; U/M: EA; Cap_F: 0.00000000033; Tolerance_%: 5; Value1: Unknown; VDC_V: 50; Value2: 50V; TaMin_C: -55; TaMax_C: 125; Cap_Case: 0402; AEC Category: Q200
C132 C135 = C3216X5R1V226M160AC: CAP, CERM, 22 µF, 35 V, +/- 20%, X5R, 1206_190; Manufacturer: TDK; Polarized: N; CompType: Capacitor; Value: 22uF; U/M: EA; Cap_F: 0.000022; Tolerance_%: 20; ESR_ohm: 0.002246; Value1: 0.002246 ohm; VDC_V: 35; Value2: 35V; TaMin_C: -55; TaMax_C: 85; Cap_Case: 1206; AEC Category: Q200
C137 = C1005X5R1C105K050BC: CAP, CERM, 1 µF, 16 V, +/- 10%, X5R, 0402; Manufacturer: TDK; Polarized: N; CompType: Capacitor; Value: 1uF; U/M: EA; Cap_F: 0.000001; Tolerance_%: 10; Value1: Unknown; VDC_V: 16; Value2: 16V; TaMin_C: -55; TaMax_C: 85; AEC Category: Q200
C138 C139 = GRM155R61C473KA01D: CAP, CERM, 0.047 µF, 16 V, +/- 10%, X5R, 0402; Manufacturer: MuRata; Polarized: N; CompType: Capacitor; Value: 0.047uF; U/M: EA; Cap_F: 0.000000047; Tolerance_%: 10; Value1: Unknown; VDC_V: 16; Value2: 16V; TaMin_C: -55; TaMax_C: 85; AEC Category: Q200
C140 = GRM1555C1H330JA01D: CAP, CERM, 33 pF, 50 V, +/- 5%, C0G/NP0, 0402; Manufacturer: MuRata; Polarized: N; CompType: Capacitor; Value: 33pF; U/M: EA; Cap_F: 0.000000000033; Tolerance_%: 5; Value1: Unknown; VDC_V: 50; Value2: 50V; TaMin_C: -55; TaMax_C: 125; AEC Category: Q200; SizeArea_mm2: 0.5; SizeAreaWB_mm2: 3; SizeX_mm: 1; SizeZ_mm: 0.6
C142 = GRM1555C1H150JA01D: CAP, CERM, 15 pF, 50 V, +/- 5%, C0G/NP0, 0402; Manufacturer: MuRata; Polarized: N; CompType: Capacitor; Value: 15pF; U/M: EA; Cap_F: 0.000000000015; Tolerance_%: 5; Value1: Unknown; VDC_V: 50; Value2: 50V; TaMin_C: -55; TaMax_C: 125; AEC Category: Q200
C143 = GRM155R71H182KA01D: CAP, CERM, 1800 pF, 50 V, +/- 10%, X7R, 0402; Manufacturer: MuRata; Polarized: N; CompType: Capacitor; Value: 1800pF; U/M: EA; Cap_F: 0.0000000018; Tolerance_%: 10; Value1: Unknown; VDC_V: 50; Value2: 50V; TaMin_C: -55; TaMax_C: 125; AEC Category: Q200
C144 = GRM1555C1H681JA01D: CAP, CERM, 680 pF, 50 V, +/- 5%, C0G/NP0, 0402; Manufacturer: MuRata; Polarized: N; CompType: Capacitor; Value: 680pF; U/M: EA; Cap_F: 0.00000000068; Tolerance_%: 5; Value1: Unknown; VDC_V: 50; Value2: 50V; TaMin_C: -55; TaMax_C: 125; AEC Category: Q200
C151 = C1005X5R1C225K050BC: CAP, CERM, 2.2 µF, 16 V, +/- 10%, X5R, 0402; Manufacturer: TDK; Polarized: N; CompType: Capacitor; Value: 2.2uF; U/M: EA; Cap_F: 0.0000022; Tolerance_%: 10; Value1: Unknown; VDC_V: 16; Value2: 16V; TaMin_C: -55; TaMax_C: 85; AEC Category: Q200
C152 C153 = GRM1555C1H101JA01D: CAP, CERM, 100 pF, 50 V, +/- 5%, C0G/NP0, 0402; Manufacturer: MuRata; Polarized: N; CompType: Capacitor; Value: 100pF; U/M: EA; Cap_F: 0.0000000001; Tolerance_%: 5; Value1: Unknown; VDC_V: 50; Value2: 50V; TaMin_C: -55; TaMax_C: 125; AEC Category: Q200
D1 = CDSOD323-T24S: Diode, TVS, Uni, 24 V, 49 Vc, SOD-323; Manufacturer: Bourns; U/M: EA; Value1: W; Vr_V: 24; AEC Category: Q101; AEC Qualified: N; SizeAreaWB_mm2: 8.695; SizeArea_mm2: 3.645; SizeX_mm: 2.7; SizeY_mm: 1.35; SizeZ_mm: 1
D4 D6 = CMP-0005844-2: Diode, Zener, 15 V, 300 mW, SOD-323; Manufacturer: NXP Semiconductor; Power_W: 300mW; SizeAreaWB_mm2: 8.695; Value1: 0.3W; RJA_CperW: 415; U/M: EA; SizeZ_mm: 1; SizeX_mm: 2.7; SizeY_mm: 1.35; SizeArea_mm2: 3.645; AEC Category: Q101
D5 = BAS 52-02V H6327: Diode, Schottky, 45 V, 0.75 A, SOD-523; Manufacturer: Infineon Technologies; U/M: EA; Vf_V: 0.6; Value: 45V; Value1: 0.75A; Value2: 0.6V; Io_A: 0.75; Vr_V: 45; TJmax_C: 150; AEC Category: Q101
D7 D8 = CMP-0082069-1: Diode, Switching, 75 V, 0.15 A, SOD-323; Manufacturer: Micro Commercial Components; Io_A: 1.5dA; SizeAreaWB_mm2: 8.695; Vr_V: 75V; Value1: 0.15A; TJmax_C: 150°C; Value: 75V; SizeZ_mm: 1; SizeX_mm: 2.7; SizeY_mm: 1.35; Vf_V: 1V; SizeArea_mm2: 3.645; AEC Qualified: N; AEC Category: Q101; RJC_CperW: 625
D9 = RB521S30T1G: Diode, Schottky, 30 V, 0.2 A, AEC-Q101, SOD-523; Manufacturer: ON Semiconductor; U/M: EA; Vf_V: 0.5; Value: 30V; Value1: 0.2A; Value2: 0.5V; Io_A: 0.2; Vr_V: 30; TJmax_C: 125; AEC Category: Q101; AEC Qualified: Y
D12-D15 = LTST-C190GKT: LED, Green, SMD; Manufacturer: Lite-On; Vf_V: 2.1; Value2: 2.1V; Io_A: 0.02; Power_TotalModule: 0.1; Value1: 0.1W; U/M: EA
D16 = LTST-C190KFKT: LED, Orange, SMD; Manufacturer: Lite-On; Type: AlInGaP; Vf_V: 2; Value2: 2V; Io_A: 0.02; Power_TotalModule: 0.075; Value1: 0.075W; U/M: EA
J1 = 12401610E4#2A: Receptacle, 0.5mm, USB TYPE C, R/A, SMT; Manufacturer: Amphenol Canada; SymbolCreator: Altium; Pitch_mm: 0.5; Gender: Female; Row_Count: 2; ContactFinish: Tin; Current_A: 5; Cert_UL: Y; Green_Lifecycle: Not Set; Green_REACh: Incomplete
J2 J3 = FLE-107-01-G-DV: Receptacle, 1.27mm, 7x2, Gold, SMT; Manufacturer: Samtec; SymbolCreator: a0412235; CompType: Socket Strip; Pitch_mm: 1.27; Gender: Female; Row_Count: 2
J4 = 614 104 150 121: Connector, Receptacle, USB Type A, R/A, Bottom Mount TH; Manufacturer: Wurth Elektronik; SymbolCreator: a0412235; Gender: Female
L5 = XFL4020-222MEB: Inductor, Shielded, Composite, 2.2 µH, 3.7 A, 0.02 ohm, SMD; Manufacturer: Coilcraft; Value: 2.2uH; Ind_H: 2.2E-6; Imax_A: 3.7; Irms: 8A @ 40C rise; Isat: 3.7A @ 30% inductance drop; DCR_ohm: 0.02; Value2: 3.7A; AEC Category: Q200
L8 = XEL6060-222MEB: Inductor, Shielded, 2.2 µH, 16 A, 0.0067 ohm, AEC-Q200 Grade 1, SMD; Manufacturer: Coilcraft; Value: 2.2uH; Ind_H: 2.2E-6; Imax_A: 16; Irms: 18.1A @ 40C rise; Isat: 16A @ 30% inductance drop; DCR_ohm: 0.0067; Value2: 16A; AEC Category: Q200; AEC Qualified: Y; AEC Grade: 1; SizeAreaWB_mm2: 71.5616; SizeArea_mm2: 41.7216; SizeX_mm: 6.36; SizeY_mm: 6.56; SizeZ_mm: 6.1
NT1 = Net-Tie: Single point connection between nets.; SymbolCreator: codlsc
Q1 Q11 = CSD16323Q3: MOSFET, N-CH, 25 V, 60 A, DQG0008A (VSON-CLIP-8); Manufacturer: Texas Instruments; Alternate Manufacturer: None; U/M: EA; ChType: N; Value: 25V; VdsMax_V: 25; Value1: 0.0044 ohm; Rdson45_ohm: 0.0044; Value2: 6.2 nC; QgTyp_nC: 6.2; Vgs_V: 10; IdsMax_A: 60; AEC Category: Q101; SizeAreaWB_mm2: 18.49; SizeArea_mm2: 10.89; SizeX_mm: 3.3; SizeZ_mm: 1.1
Q2 = CSD25404Q3: MOSFET, P-CH, -20 V, -60 A, VSON-CLIP-8; Manufacturer: Texas Instruments; Alternate Manufacturer: None; U/M: EA; ChType: P; Value: -20V; Value1: 0.0065 ohm; Rdson45_ohm: 0.0065; Value2: 10.8 nC; QgTyp_nC: 10.8; Vgs_V: -12; AEC Category: Q101; AEC Qualified: N; SymbolCreator: a0799628
Q3 Q4 = CMP-0081533-1: MOSFET, P-CH, -30 V, -35 A, PowerPAK 1212; Manufacturer: Vishay-Siliconix; Alternate Manufacturer: None; ChType: P; Value: -30V; Value1: 0.013 ohm; Rdson45_ohm: 0.013; Value2: 68 nC; QgTyp_nC: 68; Vgs_V: -25V; IdsMax_A: -35A; AEC Category: Q101; AEC Qualified: N; SizeAreaWB_mm2: 18.49; SizeArea_mm2: 10.89; SizeX_mm: 3.3; SizeZ_mm: 1.04
Q5-Q8 = CSD17308Q3: MOSFET, N-CH, 30 V, 47 A, DQG0008A (VSON-CLIP-8); Manufacturer: Texas Instruments; Alternate Manufacturer: None; U/M: EA; ChType: N; Value: 30V; VdsMax_V: 30; Value1: 0.0094 ohm; Rdson45_ohm: 0.0094; Value2: 3.9 nC; QgTyp_nC: 3.9; Vgs_V: 10; IdsMax_A: 47; AEC Category: Q101; SizeAreaWB_mm2: 18.49; SizeArea_mm2: 10.89; SizeX_mm: 3.3; SizeZ_mm: 1.1
Q14 = CMP-0081321-1: Transistor, NPN, 12 V, 2 A, SOT-23; Manufacturer: ON Semiconductor; CompType: BJT; PNP: 0; NPN: 1; Vceo_V: 12V; Vcesat1_V: 68mV; Value: 12 V; IcRated_A: 2A; Value1: 2 A; HfeMax: 330; TaMin_C: -55°C; TaMax_C: 150°C; U/M: EA; AEC Category: Q101; AEC Qualified: N; SizeAreaWB_mm2: 14; SizeArea_mm2: 7.5; SizeZ_mm: 1.1; SizeY_mm: 3; SizeX_mm: 2.5
R1 R2 R47 R53 = CRCW080533R0JNEA: RES, 33, 5%, 0.125 W, 0805; Manufacturer: Vishay-Dale; CompType: Resistor; Value: 33; U/M: EA; Value_Code: 33R0; Tolerance_%: 5; Power_W: 0.125; Value2: 0.125W; VDC_V: 150; TempCo: 200 ppm/C; EIA_Code: E24; AEC Category: Q200; SizeArea_mm2: 2.5; SizeX_mm: 2; SizeY_mm: 1.25; SizeZ_mm: 1.45; Green_Lifecycle: Active; Green_REACh: Passed
R3 R6 = CRCW04024R99FKED: RES, 4.99, 1%, 0.063 W, 0402; Manufacturer: Vishay-Dale; CompType: Resistor; Value: 4.99; U/M: EA; Value_Code: 4R99; Tolerance_%: 1; Power_W: 0.063; Value2: 0.063W; VDC_V: 50; TempCo: 100 ppm/C; EIA_Code: E96; AEC Category: Q200; SizeArea_mm2: 0.5; SizeZ_mm: 0.6
R4 = CRCW040210M0JNED: RES, 10 M, 5%, 0.063 W, 0402; Manufacturer: Vishay-Dale; CompType: Resistor; Value: 10Meg; U/M: EA; Res_ohm: 10000000; Value_Code: 10M0; Tolerance_%: 5; Power_W: 0.063; Value2: 0.063W; VDC_V: 50; TempCo: 200 ppm/C; EIA_Code: E24; AEC Category: Q200; SizeArea_mm2: 0.5; SizeX_mm: 1; SizeZ_mm: 0.6; Green_Lifecycle: Active; Green_REACh: Passed
R5 = CRCW04023M00JNED: RES, 3.0 M, 5%, 0.063 W, 0402; Manufacturer: Vishay-Dale; CompType: Resistor; Value: 3.0Meg; U/M: EA; Res_ohm: 3000000; Value_Code: 3M00; Tolerance_%: 5; Power_W: 0.063; Value2: 0.063W; VDC_V: 50; TempCo: 200 ppm/C; EIA_Code: E24; AEC Category: Q200; SizeArea_mm2: 0.5; SizeX_mm: 1; SizeZ_mm: 0.6
R8 = CRCW04021R00JNED: RES, 1.0, 5%, 0.063 W, 0402; Manufacturer: Vishay-Dale; CompType: Resistor; Value: 1.0; U/M: EA; Res_ohm: 1; Value_Code: 1R00; Tolerance_%: 5; Power_W: 0.063; Value2: 0.063W; VDC_V: 50; TempCo: 200 ppm/C; EIA_Code: E24; AEC Category: Q200; SizeArea_mm2: 0.5; SizeZ_mm: 0.6
R9 R119 = CMP-0026727-1: RES, 1.00 M, 1%, 0.063 W, 0402; Manufacturer: Yageo America; Power_W: 63mW; TempCo: 100 ppm/C; Value_Code: 1M00; U/M: EA; Value: 1.00Meg; EIA_Code: E96; Res_ohm: 1M; SizeX_mm: 1; SizeY_mm: 0.5; SizeZ_mm: 0.6; Value2: 0.063W; AEC Category: Q200
R11-R13 R16 R19 = CRCW04020000Z0ED: RES, 0, 5%, 0.063 W, 0402; Manufacturer: Vishay-Dale; CompType: Resistor; Value: 0; U/M: EA; Value_Code: 0000; Tolerance_%: 5; Power_W: 0.063; Value2: 0.063W; VDC_V: 50; TempCo: 200 ppm/C; EIA_Code: E24; AEC Category: Q200; SizeArea_mm2: 0.5; SizeX_mm: 1; SizeZ_mm: 0.6; Green_Lifecycle: Active; Green_REACh: Passed
R14 = CRCW040210K0FKED: RES, 10.0 k, 1%, 0.063 W, 0402; Manufacturer: Vishay-Dale; CompType: Resistor; Value: 10.0k; U/M: EA; Res_ohm: 10000; Value_Code: 10k0; Tolerance_%: 1; Power_W: 0.063; Value2: 0.063W; VDC_V: 50; TempCo: 100 ppm/C; EIA_Code: E96; AEC Category: Q200; SizeArea_mm2: 0.5; SizeZ_mm: 0.6; Green_Lifecycle: Active; Green_REACh: Passed
R15 = CRCW0402470KJNED: RES, 470 k, 5%, 0.063 W, 0402; Manufacturer: Vishay-Dale; CompType: Resistor; Value: 470k; U/M: EA; Res_ohm: 470000; Tolerance_%: 5; Power_W: 0.063; Value2: 0.063W; VDC_V: 50; TempCo: 200 ppm/C; EIA_Code: E24; AEC Category: Q200; SizeArea_mm2: 0.5; SizeX_mm: 1; SizeZ_mm: 0.6
R17 = CRCW0402196KFKED: RES, 196 k, 1%, 0.063 W, 0402; Manufacturer: Vishay-Dale; CompType: Resistor; Value: 196k; U/M: EA; Res_ohm: 196000; Tolerance_%: 1; Power_W: 0.063; Value2: 0.063W; VDC_V: 50; TempCo: 100 ppm/C; EIA_Code: E96; AEC Category: Q200; SizeArea_mm2: 0.5; SizeZ_mm: 0.6; Green_Lifecycle: Active; Green_REACh: Passed
R18 = CRCW04021M00JNED: RES, 1.0 M, 5%, 0.063 W, 0402; Manufacturer: Vishay-Dale; CompType: Resistor; Value: 1.0Meg; U/M: EA; Res_ohm: 1000000; Value_Code: 1M00; Tolerance_%: 5; Power_W: 0.063; Value2: 0.063W; VDC_V: 50; TempCo: 200 ppm/C; EIA_Code: E24; AEC Category: Q200; SizeArea_mm2: 0.5; SizeX_mm: 1; SizeZ_mm: 0.6; Green_Lifecycle: Active; Green_REACh: Passed
R22 R122 = CMP-0026815-1: RES, 100 k, 0.1%, 0.063 W, 0402; Manufacturer: Susumu Co Ltd; Power_W: 63mW; TempCo: 25 ppm/C; U/M: EA; Value: 100k; EIA_Code: E192; SizeX_mm: 1; SizeY_mm: 0.5; SizeZ_mm: 0.6; Value2: 0.063W; AEC Category: Q200
R34 R35 R76 R77 R81 R113 = CRCW04020000Z0ED: RES, 0, 5%, 0.063 W, 0402; Manufacturer: Vishay-Dale; CompType: Resistor; Value: 0; U/M: EA; Value_Code: 0000; Tolerance_%: 5; Power_W: 0.063; Value2: 0.063W; VDC_V: 50; TempCo: 200 ppm/C; EIA_Code: E24; AEC Category: Q200
R45 = CRCW04021K00JNED: RES, 1.0 k, 5%, 0.063 W, 0402; Manufacturer: Vishay-Dale; CompType: Resistor; Value: 1.0k; U/M: EA; Res_ohm: 1000; Value_Code: 1k00; Tolerance_%: 5; Power_W: 0.063; Value2: 0.063W; VDC_V: 50; TempCo: 200 ppm/C; EIA_Code: E24; AEC Category: Q200
R55 R57 = CRCW04025K10JNED: RES, 5.1 k, 5%, 0.063 W, 0402; Manufacturer: Vishay-Dale; CompType: Resistor; Value: 5.1k; U/M: EA; Res_ohm: 5100; Value_Code: 5k10; Tolerance_%: 5; Power_W: 0.063; Value2: 0.063W; VDC_V: 50; TempCo: 200 ppm/C; EIA_Code: E24; AEC Category: Q200
R59 = ERT-J0EG103HA: Thermistor NTC, 10k ohm, 3%, 0402; Manufacturer: Panasonic; U/M: EA; Tolerance_%: 3; Power_W: 0.066; TaMin_C: -40; TaMax_C: 125
R60 R72 R73 = WSLP1206R0100FEA: RES, 0.01, 1%, 1 W, 1206; Manufacturer: Vishay-Dale; CompType: Resistor; Value: 0.01; U/M: EA; Value_Code: R010; Tolerance_%: 1; Value2: 1W; TempCo: 75 ppm/C; EIA_Code: E96; AEC Category: Q200
R62 R63 = CRCW0402100RFKED: RES, 100, 1%, 0.063 W, 0402; Manufacturer: Vishay-Dale; CompType: Resistor; Value: 100; U/M: EA; Value_Code: 100R; Tolerance_%: 1; Power_W: 0.063; Value2: 0.063W; VDC_V: 50; TempCo: 100 ppm/C; EIA_Code: E96; AEC Category: Q200
R78 R79 R84 = CRCW040210R0JNED: RES, 10, 5%, 0.063 W, 0402; Manufacturer: Vishay-Dale; CompType: Resistor; Value: 10; U/M: EA; Value_Code: 10R0; Tolerance_%: 5; Power_W: 0.063; Value2: 0.063W; VDC_V: 50; TempCo: 200 ppm/C; EIA_Code: E24; AEC Category: Q200
R82 R83 = CRCW060356R0JNEA: RES, 56, 5%, 0.1 W, 0603; Manufacturer: Vishay-Dale; CompType: Resistor; Value: 56; U/M: EA; Value_Code: 56R0; Tolerance_%: 5; Power_W: 0.1; Value2: 0.1W; VDC_V: 75; TempCo: 200 ppm/C; EIA_Code: E24; AEC Category: Q200
R86 = CRCW040240K2FKED: RES, 40.2 k, 1%, 0.063 W, 0402; Manufacturer: Vishay-Dale; CompType: Resistor; Value: 40.2k; U/M: EA; Res_ohm: 40200; Value_Code: 40k2; Tolerance_%: 1; Power_W: 0.063; Value2: 0.063W; VDC_V: 50; TempCo: 100 ppm/C; EIA_Code: E96; AEC Category: Q200
R87 = CRCW040210K0FKED: RES, 10.0 k, 1%, 0.063 W, 0402; Manufacturer: Vishay-Dale; CompType: Resistor; Value: 10.0k; U/M: EA; Res_ohm: 10000; Value_Code: 10k0; Tolerance_%: 1; Power_W: 0.063; Value2: 0.063W; VDC_V: 50; TempCo: 100 ppm/C; EIA_Code: E96; AEC Category: Q200; SizeArea_mm2: 0.5; SizeZ_mm: 0.6
R92 = CRCW0402383KFKED: RES, 383 k, 1%, 0.063 W, 0402; Manufacturer: Vishay-Dale; CompType: Resistor; Value: 383k; U/M: EA; Res_ohm: 383000; Tolerance_%: 1; Power_W: 0.063; Value2: 0.063W; VDC_V: 50; TempCo: 100 ppm/C; EIA_Code: E96; AEC Category: Q200
R93 = CRCW040280K6FKED: RES, 80.6 k, 1%, 0.063 W, 0402; Manufacturer: Vishay-Dale; CompType: Resistor; Value: 80.6k; U/M: EA; Res_ohm: 80600; Value_Code: 80k6; Tolerance_%: 1; Power_W: 0.063; Value2: 0.063W; VDC_V: 50; TempCo: 100 ppm/C; EIA_Code: E96; AEC Category: Q200; SizeArea_mm2: 0.5; SizeZ_mm: 0.6; Green_Lifecycle: Active; Green_REACh: Passed
R94 = CRCW0402221KFKED: RES, 221 k, 1%, 0.063 W, 0402; Manufacturer: Vishay-Dale; CompType: Resistor; Value: 221k; U/M: EA; Res_ohm: 221000; Tolerance_%: 1; Power_W: 0.063; Value2: 0.063W; VDC_V: 50; TempCo: 100 ppm/C; EIA_Code: E96; AEC Category: Q200
R95 = CRCW0402100KFKED: RES, 100 k, 1%, 0.063 W, 0402; Manufacturer: Vishay-Dale; CompType: Resistor; Value: 100k; U/M: EA; Res_ohm: 100000; Tolerance_%: 1; Power_W: 0.063; Value2: 0.063W; VDC_V: 50; TempCo: 100 ppm/C; EIA_Code: E96; AEC Category: Q200
R98 = CRCW0402137KFKED: RES, 137 k, 1%, 0.063 W, 0402; Manufacturer: Vishay-Dale; CompType: Resistor; Value: 137k; U/M: EA; Res_ohm: 137000; Tolerance_%: 1; Power_W: 0.063; Value2: 0.063W; VDC_V: 50; TempCo: 100 ppm/C; EIA_Code: E96; AEC Category: Q200; SizeArea_mm2: 0.5; SizeZ_mm: 0.6
R99 = CRCW040230K1FKED: RES, 30.1 k, 1%, 0.063 W, 0402; Manufacturer: Vishay-Dale; CompType: Resistor; Value: 30.1k; U/M: EA; Res_ohm: 30100; Value_Code: 30k1; Tolerance_%: 1; Power_W: 0.063; Value2: 0.063W; VDC_V: 50; TempCo: 100 ppm/C; EIA_Code: E96; AEC Category: Q200
R100-R104 = CRCW04023K30JNED: RES, 3.3 k, 5%, 0.063 W, 0402; Manufacturer: Vishay-Dale; CompType: Resistor; Value: 3.3k; U/M: EA; Res_ohm: 3300; Value_Code: 3k30; Tolerance_%: 5; Power_W: 0.063; Value2: 0.063W; VDC_V: 50; TempCo: 200 ppm/C; EIA_Code: E24
R105 = CRCW0402665KFKED: RES, 665 k, 1%, 0.063 W, 0402; Manufacturer: Vishay-Dale; CompType: Resistor; Value: 665k; U/M: EA; Res_ohm: 665000; Tolerance_%: 1; Power_W: 0.063; Value2: 0.063W; VDC_V: 50; TempCo: 100 ppm/C; EIA_Code: E96; AEC Category: Q200
R106 = CRCW0402130KFKED: RES, 130 k, 1%, 0.063 W, 0402; Manufacturer: Vishay-Dale; CompType: Resistor; Value: 130k; U/M: EA; Res_ohm: 130000; Tolerance_%: 1; Power_W: 0.063; Value2: 0.063W; VDC_V: 50; TempCo: 100 ppm/C; EIA_Code: E96; AEC Category: Q200
R112 = ERJ-8CWFR050V: RES, 0.05, 1%, 1 W, 1206; Manufacturer: Panasonic; CompType: Resistor; Value: 0.05; U/M: EA; Value_Code: R050; Tolerance_%: 1; Value2: 1W; TempCo: 50 ppm/C; EIA_Code: E96
U1 = CMP-0079371-1: I2C Narrow VDC Buck-Boost Battery Charge Controller With System Power Monitor and Processor Hot Monitor, RSN0032B (WQFN-32); Alternate PartNumber: BQ25713RSNT; Alternate Manufacturer: Texas Instruments; SizeAreaWB_mm2: 25; SizeZ_mm: 0.8; SizeX_mm: 4; SizeArea_mm2: 16; CompType: IC; AEC Qualified: N; AEC Category: Q200
U7 = CMP-0077526-4: 3-5S Ultra Low-Power Voltage, Current, Temperature, and Open Wire Stackable Lithium-ion Battery Protector with Smart Cell Balancing, PW0024A (TSSOP-24); Manufacturer: Texas Instruments; SizeArea_mm2: 49.92; CompType: IC; SizeAreaWB_mm2: 82.32; SizeY_mm: 7.8; SizeZ_mm: 1.2; U/M: EA; SizeX_mm: 6.4; AEC Category: Q200; AEC Qualified: N
U8 = TLV62130RGTR: 4-17V 3A Step-Down Converter with DCS-Control, RGT0016C; Alternate PartNumber: TLV62130RGTT; Manufacturer: Texas Instruments; SymbolCreator: a0411947; CompType: IC; U/M: EA
U9 = TPS2514ADBVR: USB Dedicated Charging Port Controller, DBV0006A; Alternate PartNumber: TPS2514ADBVT; Manufacturer: Texas Instruments; SymbolCreator: a0411947; CompType: IC; U/M: EA
U10 = TPD2E1B06DRLR: DUAL CHANNEL HIGH SPEED ESD PROTECTION DEVICE, DRL0006A; Manufacturer: Texas Instruments; SymbolCreator: a0411947; CompType: IC; U/M: EA
ZZ1 = AssemblyNoteLabel: SymbolCreator: a0412235
ZZ2-ZZ4 = AssemblyNote: SymbolCreator: codlsc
